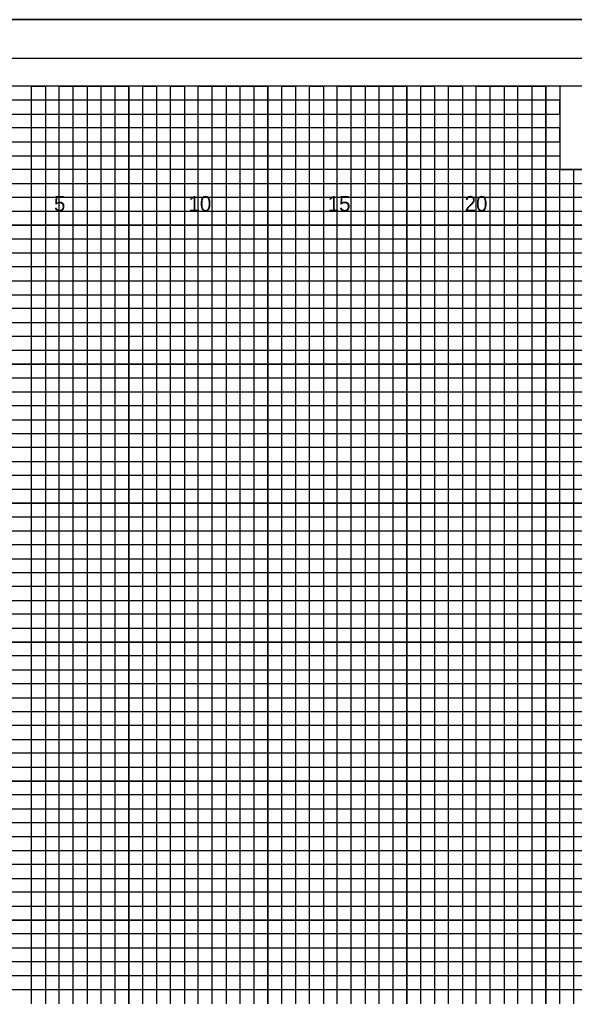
# Model space of a CAD drawing. Extents: x -4 to 103, y -2 to 209.
# Drawn here: x 54.82 to 74.78, y 103.08 to 138.22 of the extents above; entities that cross this region are included whole.
import ezdxf

# ---------------------------------------------------------------- set-up
doc = ezdxf.new("R2010")
doc.units = 0
for name, color, linetype in [('Exist XS Ground Line', 7, 'Continuous'), ('Old_Level_10', 7, 'Continuous'), ('Old_Level_3', 7, 'Continuous'), ('Old_Level_5', 7, 'Continuous'), ('Old_Level_8', 7, 'Continuous'), ('Prop XS Dump Level', 7, 'Continuous'), ('Prop XS Elevation Labels', 7, 'Continuous'), ('Prop XS Finish Grade', 7, 'Continuous')]:
    doc.layers.add(name, color=color, linetype=linetype)

msp = doc.modelspace()

# ---------------------------------------------------------------- linework, layer by layer
at = {"layer": 'Exist XS Ground Line'}
msp.add_lwpolyline([(103, 136.825), (-2.8, 136.825), (-2.8, 69.825), (103, 69.825)], close=True, dxfattribs=at)
at = {"layer": 'Old_Level_10'}
for p, q in [((56.25, 70.825), (56.25, 135.825)), ((58.75, 70.825), (58.75, 135.825)), ((61.25, 70.825), (61.25, 135.825)), ((63.75, 70.825), (63.75, 135.825)), ((66.25, 70.825), (66.25, 135.825)), ((68.75, 70.825), (68.75, 135.825)), ((71.25, 70.825), (71.25, 135.825)), ((73.75, 70.825), (73.75, 135.825)), ((0, 133.325), (74.25, 133.325)), ((0, 130.825), (102.5, 130.825)), ((0, 128.325), (102.5, 128.325)), ((0, 125.825), (102.5, 125.825)), ((0, 123.325), (102.5, 123.325)), ((0, 120.825), (102.5, 120.825)), ((0, 118.325), (102.5, 118.325)), ((0, 115.825), (102.5, 115.825)), ((0, 113.325), (102.5, 113.325)), ((0, 110.825), (102.5, 110.825)), ((0, 108.325), (102.5, 108.325)), ((0, 105.825), (102.5, 105.825)), ((0, 103.325), (102.5, 103.325))]:
    msp.add_line(p, q, dxfattribs=at)
at = {"layer": 'Old_Level_3'}
msp.add_line((-3.5, 138.225), (103.4, 138.225), dxfattribs=at)
at = {"layer": 'Old_Level_5'}
msp.add_lwpolyline([(103.4, 138.225), (-3.5, 138.225), (-3.5, 68.4), (103.4, 68.4)], close=True, dxfattribs=at)
at = {"layer": 'Old_Level_8'}
for points in [[(56.25, 70.825), (56.25, 135.825), (58.75, 135.825), (58.75, 70.825)], [(61.25, 70.825), (61.25, 135.825), (63.75, 135.825), (63.75, 70.825)], [(66.25, 70.825), (66.25, 135.825), (68.75, 135.825), (68.75, 70.825)], [(71.25, 70.825), (71.25, 135.825), (73.75, 135.825), (73.75, 70.825)], [(0, 133.325), (74.25, 133.325)], [(0, 128.325), (102.5, 128.325), (102.5, 130.825), (0, 130.825)], [(0, 123.325), (102.5, 123.325), (102.5, 125.825), (0, 125.825)], [(0, 118.325), (102.5, 118.325), (102.5, 120.825), (0, 120.825)], [(0, 113.325), (102.5, 113.325), (102.5, 115.825), (0, 115.825)], [(0, 108.325), (102.5, 108.325), (102.5, 110.825), (0, 110.825)], [(0, 103.325), (102.5, 103.325), (102.5, 105.825), (0, 105.825)]]:
    msp.add_lwpolyline(points, dxfattribs=at)
at = {"layer": 'Prop XS Dump Level'}
for points in [[(102.5, 135.825), (0, 135.825), (0, 70.825), (102.5, 70.825)], [(83.75, 135.825), (74.25, 135.825), (74.25, 132.825), (83.75, 132.825)]]:
    msp.add_lwpolyline(points, close=True, dxfattribs=at)
at = {"layer": 'Prop XS Finish Grade'}
for points in [[(55.25, 70.825), (55.25, 135.825), (55.75, 135.825), (55.75, 70.825)], [(56.75, 70.825), (56.75, 135.825), (57.25, 135.825), (57.25, 70.825)], [(57.75, 70.825), (57.75, 135.825), (58.25, 135.825), (58.25, 70.825)], [(59.25, 70.825), (59.25, 135.825), (59.75, 135.825), (59.75, 70.825)], [(60.25, 70.825), (60.25, 135.825), (60.75, 135.825), (60.75, 70.825)], [(61.75, 70.825), (61.75, 135.825), (62.25, 135.825), (62.25, 70.825)], [(62.75, 70.825), (62.75, 135.825), (63.25, 135.825), (63.25, 70.825)], [(64.25, 70.825), (64.25, 135.825), (64.75, 135.825), (64.75, 70.825)], [(65.25, 70.825), (65.25, 135.825), (65.75, 135.825), (65.75, 70.825)], [(66.75, 70.825), (66.75, 135.825), (67.25, 135.825), (67.25, 70.825)], [(67.75, 70.825), (67.75, 135.825), (68.25, 135.825), (68.25, 70.825)], [(69.25, 70.825), (69.25, 135.825)], [(69.25, 135.825), (69.75, 135.825), (69.75, 70.825)], [(70.25, 70.825), (70.25, 135.825), (70.75, 135.825), (70.75, 70.825)], [(71.75, 70.825), (71.75, 135.825), (72.25, 135.825), (72.25, 70.825)], [(72.75, 70.825), (72.75, 135.825), (73.25, 135.825), (73.25, 70.825)], [(0, 132.825), (0, 133.825), (74.25, 133.825), (74.25, 134.325), (0, 134.325), (0, 134.825), (74.25, 134.825), (74.25, 135.325), (0, 135.325)], [(0, 132.325), (102.5, 132.325), (102.5, 132.825), (0, 132.825)], [(74.25, 70.825), (74.25, 132.825), (74.75, 132.825), (74.75, 70.825)], [(0, 131.325), (102.5, 131.325), (102.5, 131.825), (0, 131.825)], [(0, 129.825), (102.5, 129.825), (102.5, 130.325), (0, 130.325)], [(0, 128.825), (102.5, 128.825), (102.5, 129.325), (0, 129.325)], [(0, 127.325), (102.5, 127.325), (102.5, 127.825), (0, 127.825)], [(0, 126.325), (102.5, 126.325), (102.5, 126.825), (0, 126.825)], [(0, 124.825), (102.5, 124.825), (102.5, 125.325), (0, 125.325)], [(0, 123.825), (102.5, 123.825), (102.5, 124.325), (0, 124.325)], [(0, 122.325), (102.5, 122.325), (102.5, 122.825), (0, 122.825)], [(0, 121.325), (102.5, 121.325), (102.5, 121.825), (0, 121.825)], [(0, 119.825), (102.5, 119.825), (102.5, 120.325), (0, 120.325)], [(0, 118.825), (102.5, 118.825), (102.5, 119.325), (0, 119.325)], [(0, 117.325), (102.5, 117.325), (102.5, 117.825), (0, 117.825)], [(0, 116.325), (102.5, 116.325), (102.5, 116.825), (0, 116.825)], [(0, 114.825), (102.5, 114.825), (102.5, 115.325), (0, 115.325)], [(0, 113.825), (102.5, 113.825), (102.5, 114.325), (0, 114.325)], [(0, 112.325), (102.5, 112.325), (102.5, 112.825), (0, 112.825)], [(0, 111.325), (102.5, 111.325), (102.5, 111.825), (0, 111.825)], [(0, 109.825), (102.5, 109.825), (102.5, 110.325), (0, 110.325)], [(0, 108.825), (102.5, 108.825), (102.5, 109.325), (0, 109.325)], [(0, 107.325), (102.5, 107.325), (102.5, 107.825), (0, 107.825)], [(0, 106.325), (102.5, 106.325), (102.5, 106.825), (0, 106.825)], [(0, 104.825), (102.5, 104.825), (102.5, 105.325), (0, 105.325)], [(0, 103.825), (102.5, 103.825), (102.5, 104.325), (0, 104.325)]]:
    msp.add_lwpolyline(points, dxfattribs=at)

# ---------------------------------------------------------------- texts
at = {"layer": 'Prop XS Elevation Labels'}
for s, p in [('5', (56.0574, 131.325)), ('10', (60.8971, 131.325)), ('15', (65.9057, 131.325)), ('20', (70.8312, 131.325))]:
    msp.add_text(s, height=0.55, dxfattribs=at).set_placement(p)

doc.saveas('drawing.dxf')
